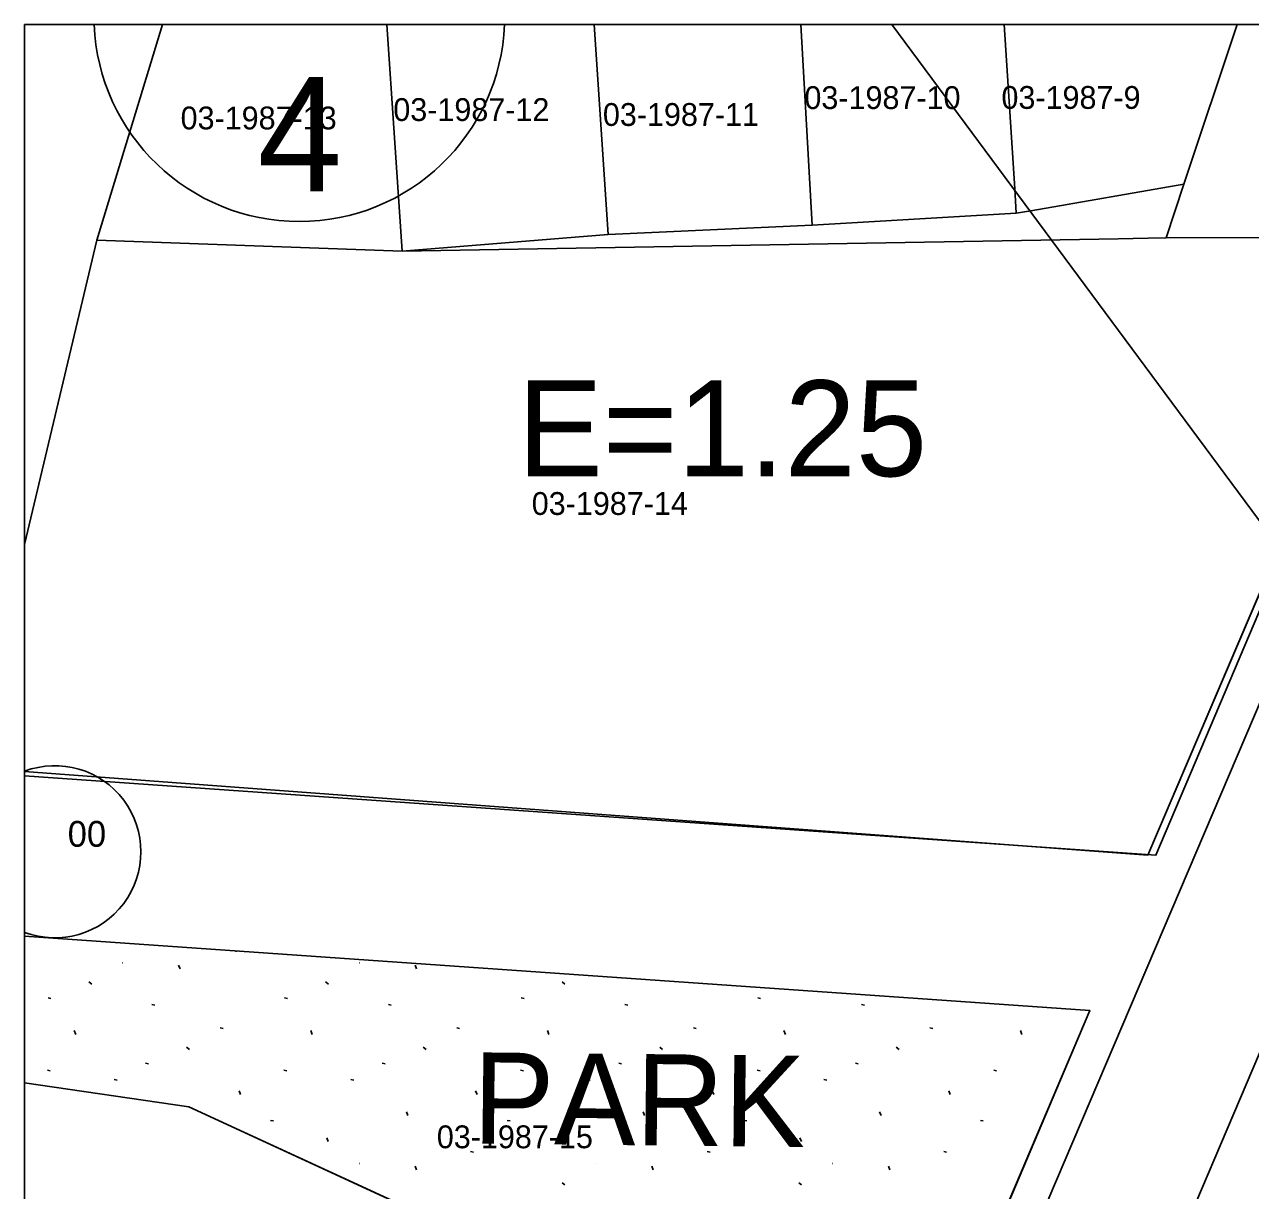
# Model space of a CAD drawing. Extents: x 413946 to 415528, y 4453939 to 4454944.
# Drawn here: x 413945.6 to 413999.3, y 4454892.9 to 4454944 of the extents above; entities that cross this region are included whole.
import ezdxf

# ---------------------------------------------------------------- set-up
doc = ezdxf.new("R2010")
doc.units = 0
for name, color, linetype in [('0_KADASTRO', 7, 'Continuous'), ('0_ÇERÇEVE', 7, 'Continuous'), ('KST_ENERJI_NAKIL_HAT', 7, 'Continuous'), ('Level 28', 7, 'Continuous'), ('Level 33', 7, 'Continuous'), ('Level 41', 7, 'Continuous'), ('Level 54', 7, 'Continuous'), ('Level 62', 7, 'Continuous'), ('SEMBOL', 7, 'Continuous')]:
    doc.layers.add(name, color=color, linetype=linetype)

msp = doc.modelspace()

# ---------------------------------------------------------------- linework, layer by layer
at = {"layer": '0_KADASTRO'}
for points in [[(413945.566, 4454921.163), (413945.566, 4454943.957), (413951.612, 4454943.957)], [(413951.612, 4454943.957), (413948.73, 4454934.5), (413945.566, 4454921.163)], [(413961.44, 4454943.957), (413962.11, 4454934.03), (413948.73, 4454934.5), (413951.612, 4454943.957)], [(413951.612, 4454943.957), (413961.44, 4454943.957)], [(413961.44, 4454943.957), (413970.525, 4454943.957)], [(413970.525, 4454943.957), (413971.15, 4454934.76), (413962.11, 4454934.03), (413961.44, 4454943.957)], [(413970.525, 4454943.957), (413979.593, 4454943.957)], [(413979.593, 4454943.957), (413980.08, 4454935.16), (413971.15, 4454934.76), (413970.525, 4454943.957)], [(413979.593, 4454943.957), (413988.501, 4454943.957)], [(413988.501, 4454943.957), (413988.96, 4454936.76), (413989.02, 4454935.69), (413980.08, 4454935.16), (413979.593, 4454943.957)], [(413988.501, 4454943.957), (413998.704, 4454943.957)], [(413998.704, 4454943.957), (413996.37, 4454936.96), (413989.67, 4454935.79), (413989.02, 4454935.69), (413988.96, 4454936.76), (413988.501, 4454943.957)], [(414010.602, 4454943.957), (414006.63, 4454934.62), (413995.6, 4454934.61), (413996.37, 4454936.96), (413998.704, 4454943.957)], [(413998.704, 4454943.957), (414010.602, 4454943.957)], [(413945.566, 4454921.163), (413948.73, 4454934.5), (413962.11, 4454934.03), (413993.49, 4454934.57), (413994.81, 4454934.6), (413995.6, 4454934.61), (414006.63, 4454934.62), (414001.63, 4454922.83), (413995.15, 4454907.55), (413945.566, 4454911.024)], [(413945.566, 4454911.024), (413945.566, 4454921.163)], [(413945.566, 4454897.575), (413945.566, 4454904)], [(413945.566, 4454904), (413992.26, 4454900.74), (413984.29, 4454882), (413952.76, 4454896.53), (413945.566, 4454897.575)]]:
    msp.add_lwpolyline(points, dxfattribs=at)
at = {"layer": '0_ÇERÇEVE'}
msp.add_lwpolyline([(413945.566, 4454943.957), (415494.137, 4454943.957), (415494.137, 4453939.478), (413945.566, 4453939.478)], close=True, dxfattribs=at)
at = {"layer": 'KST_ENERJI_NAKIL_HAT'}
msp.add_line((414041.874, 4454865.239), (413983.573, 4454943.957), dxfattribs=at)
at = {"layer": 'Level 28'}
for p, q in [((414010.329, 4454943.957), (413994.794, 4454907.558)), ((413994.794, 4454907.558), (413945.566, 4454911.228)), ((413945.566, 4454904), (413992.26, 4454900.74)), ((413992.26, 4454900.74), (413984.29, 4454882)), ((413952.76, 4454896.53), (413945.566, 4454897.575)), ((413984.29, 4454882), (413952.76, 4454896.53))]:
    msp.add_line(p, q, dxfattribs=at)
at = {"layer": 'Level 41'}
for p, q in [((413954.818, 4454903.354), (413954.874, 4454903.343)), ((413954.818, 4454903.354), (413954.874, 4454903.343)), ((413949.864, 4454902.843), (413949.872, 4454902.841)), ((413949.864, 4454902.843), (413949.872, 4454902.841)), ((413960.232, 4454902.843), (413960.24, 4454902.841)), ((413960.232, 4454902.843), (413960.24, 4454902.841)), ((413952.383, 4454902.573), (413952.319, 4454902.735)), ((413952.383, 4454902.573), (413952.319, 4454902.735)), ((413962.751, 4454902.573), (413962.687, 4454902.735)), ((413962.751, 4454902.573), (413962.687, 4454902.735)), ((413948.389, 4454902.004), (413948.516, 4454901.906)), ((413948.389, 4454902.004), (413948.516, 4454901.906)), ((413958.757, 4454902.004), (413958.884, 4454901.906)), ((413958.757, 4454902.004), (413958.884, 4454901.906)), ((413969.125, 4454902.004), (413969.252, 4454901.906)), ((413969.125, 4454902.004), (413969.252, 4454901.906)), ((413946.595, 4454901.299), (413946.721, 4454901.275)), ((413946.595, 4454901.299), (413946.721, 4454901.275)), ((413956.963, 4454901.299), (413957.089, 4454901.275)), ((413956.963, 4454901.299), (413957.089, 4454901.275)), ((413967.331, 4454901.299), (413967.457, 4454901.275)), ((413967.331, 4454901.299), (413967.457, 4454901.275)), ((413977.699, 4454901.299), (413977.825, 4454901.275)), ((413977.699, 4454901.299), (413977.825, 4454901.275)), ((413951.143, 4454901.005), (413951.27, 4454900.982)), ((413951.143, 4454901.005), (413951.27, 4454900.982)), ((413961.511, 4454901.005), (413961.638, 4454900.982)), ((413961.511, 4454901.005), (413961.638, 4454900.982)), ((413971.879, 4454901.005), (413972.006, 4454900.982)), ((413971.879, 4454901.005), (413972.006, 4454900.982)), ((413982.247, 4454901.005), (413982.374, 4454900.982)), ((413982.247, 4454901.005), (413982.374, 4454900.982)), ((413947.808, 4454899.701), (413947.743, 4454899.864)), ((413947.808, 4454899.701), (413947.743, 4454899.864)), ((413954.143, 4454899.981), (413954.268, 4454899.956)), ((413954.143, 4454899.981), (413954.268, 4454899.956)), ((413958.176, 4454899.701), (413958.111, 4454899.864)), ((413958.176, 4454899.701), (413958.111, 4454899.864)), ((413964.511, 4454899.981), (413964.636, 4454899.956)), ((413964.511, 4454899.981), (413964.636, 4454899.956)), ((413968.544, 4454899.701), (413968.479, 4454899.864)), ((413968.544, 4454899.701), (413968.479, 4454899.864)), ((413974.879, 4454899.981), (413975.004, 4454899.956)), ((413974.879, 4454899.981), (413975.004, 4454899.956)), ((413978.912, 4454899.701), (413978.847, 4454899.864)), ((413978.912, 4454899.701), (413978.847, 4454899.864)), ((413985.247, 4454899.981), (413985.372, 4454899.956)), ((413985.247, 4454899.981), (413985.372, 4454899.956)), ((413989.28, 4454899.701), (413989.215, 4454899.864)), ((413989.28, 4454899.701), (413989.215, 4454899.864)), ((413952.668, 4454899.143), (413952.795, 4454899.044)), ((413952.668, 4454899.143), (413952.795, 4454899.044)), ((413963.036, 4454899.143), (413963.163, 4454899.044)), ((413963.036, 4454899.143), (413963.163, 4454899.044)), ((413973.404, 4454899.143), (413973.531, 4454899.044)), ((413973.404, 4454899.143), (413973.531, 4454899.044)), ((413983.772, 4454899.143), (413983.899, 4454899.044)), ((413983.772, 4454899.143), (413983.899, 4454899.044)), ((413946.568, 4454898.133), (413946.695, 4454898.11)), ((413946.568, 4454898.133), (413946.695, 4454898.11)), ((413950.873, 4454898.437), (413950.999, 4454898.414)), ((413950.873, 4454898.437), (413950.999, 4454898.414)), ((413956.936, 4454898.133), (413957.063, 4454898.11)), ((413956.936, 4454898.133), (413957.063, 4454898.11)), ((413961.241, 4454898.437), (413961.367, 4454898.414)), ((413961.241, 4454898.437), (413961.367, 4454898.414)), ((413967.304, 4454898.133), (413967.431, 4454898.11)), ((413967.304, 4454898.133), (413967.431, 4454898.11)), ((413971.609, 4454898.437), (413971.735, 4454898.414)), ((413971.609, 4454898.437), (413971.735, 4454898.414)), ((413977.672, 4454898.133), (413977.799, 4454898.11)), ((413977.672, 4454898.133), (413977.799, 4454898.11)), ((413981.977, 4454898.437), (413982.103, 4454898.414)), ((413981.977, 4454898.437), (413982.103, 4454898.414)), ((413988.04, 4454898.133), (413988.167, 4454898.11)), ((413988.04, 4454898.133), (413988.167, 4454898.11)), ((413949.497, 4454897.724), (413949.624, 4454897.699)), ((413949.497, 4454897.724), (413949.624, 4454897.699)), ((413959.865, 4454897.724), (413959.992, 4454897.699)), ((413959.865, 4454897.724), (413959.992, 4454897.699)), ((413970.233, 4454897.724), (413970.36, 4454897.699)), ((413970.233, 4454897.724), (413970.36, 4454897.699)), ((413980.601, 4454897.724), (413980.728, 4454897.699)), ((413980.601, 4454897.724), (413980.728, 4454897.699)), ((413990.969, 4454897.724), (413990.977, 4454897.722)), ((413990.969, 4454897.724), (413990.977, 4454897.722)), ((413955.033, 4454897.064), (413954.967, 4454897.227)), ((413955.033, 4454897.064), (413954.967, 4454897.227)), ((413965.401, 4454897.064), (413965.335, 4454897.227)), ((413965.401, 4454897.064), (413965.335, 4454897.227)), ((413975.769, 4454897.064), (413975.703, 4454897.227)), ((413975.769, 4454897.064), (413975.703, 4454897.227)), ((413986.137, 4454897.064), (413986.071, 4454897.227)), ((413986.137, 4454897.064), (413986.071, 4454897.227)), ((413956.352, 4454895.929), (413956.478, 4454895.906)), ((413956.352, 4454895.929), (413956.478, 4454895.906)), ((413962.37, 4454896.15), (413962.305, 4454896.313)), ((413962.37, 4454896.15), (413962.305, 4454896.313)), ((413966.72, 4454895.929), (413966.846, 4454895.906)), ((413966.72, 4454895.929), (413966.846, 4454895.906)), ((413972.738, 4454896.15), (413972.673, 4454896.313)), ((413972.738, 4454896.15), (413972.673, 4454896.313)), ((413977.088, 4454895.929), (413977.214, 4454895.906)), ((413977.088, 4454895.929), (413977.214, 4454895.906)), ((413983.106, 4454896.15), (413983.041, 4454896.313)), ((413983.106, 4454896.15), (413983.041, 4454896.313)), ((413987.456, 4454895.929), (413987.582, 4454895.906)), ((413987.456, 4454895.929), (413987.582, 4454895.906)), ((413958.874, 4454895.001), (413958.81, 4454895.162)), ((413958.874, 4454895.001), (413958.81, 4454895.162)), ((413969.242, 4454895.001), (413969.178, 4454895.162)), ((413969.242, 4454895.001), (413969.178, 4454895.162)), ((413979.61, 4454895.001), (413979.546, 4454895.162)), ((413979.61, 4454895.001), (413979.546, 4454895.162)), ((413965.116, 4454894.562), (413965.242, 4454894.537)), ((413965.116, 4454894.562), (413965.242, 4454894.537)), ((413975.484, 4454894.562), (413975.61, 4454894.537)), ((413975.484, 4454894.562), (413975.61, 4454894.537)), ((413985.852, 4454894.562), (413985.978, 4454894.537)), ((413985.852, 4454894.562), (413985.978, 4454894.537)), ((413960.232, 4454894.037), (413960.24, 4454894.035)), ((413960.232, 4454894.037), (413960.24, 4454894.035)), ((413962.751, 4454893.767), (413962.687, 4454893.929)), ((413962.751, 4454893.767), (413962.687, 4454893.929)), ((413970.6, 4454894.037), (413970.608, 4454894.035)), ((413970.6, 4454894.037), (413970.608, 4454894.035)), ((413973.119, 4454893.767), (413973.055, 4454893.929)), ((413973.119, 4454893.767), (413973.055, 4454893.929)), ((413980.968, 4454894.037), (413980.976, 4454894.035)), ((413980.968, 4454894.037), (413980.976, 4454894.035)), ((413983.487, 4454893.767), (413983.423, 4454893.929)), ((413983.487, 4454893.767), (413983.423, 4454893.929)), ((413969.125, 4454893.198), (413969.252, 4454893.1)), ((413969.125, 4454893.198), (413969.252, 4454893.1)), ((413979.493, 4454893.198), (413979.62, 4454893.1)), ((413979.493, 4454893.198), (413979.62, 4454893.1))]:
    msp.add_line(p, q, dxfattribs=at)
at = {"layer": 'Level 54'}
for points in [[(414010.329, 4454943.957), (413994.794, 4454907.558), (413945.566, 4454911.228)], [(413945.566, 4454911.228), (413945.566, 4454943.957), (414010.329, 4454943.957)]]:
    msp.add_lwpolyline(points, dxfattribs=at)
at = {"layer": 'Level 62'}
for p, q in [((413980.793, 4454869.825), (414012.354, 4454943.957)), ((413986.313, 4454867.474), (414018.875, 4454943.957))]:
    msp.add_line(p, q, dxfattribs=at)
at = {"layer": 'SEMBOL'}
for points in [[(413966.601, 4454943.957), (413948.616, 4454943.957)], [(413945.566, 4454911.233), (413945.566, 4454904.173)]]:
    msp.add_lwpolyline(points, dxfattribs=at)
for centre, radius, start, end in [((413957.609, 4454944.323), 9, 182.3341, 357.6659), ((413946.894, 4454907.703), 3.772, 249.3856, 110.6144)]:
    msp.add_arc(centre, radius, start, end, dxfattribs=at)

# ---------------------------------------------------------------- texts
at = {"layer": '0_KADASTRO'}
for s, p in [('03-1987-10', (413979.745, 4454940.253)), ('03-1987-9', (413988.38, 4454940.26)), ('03-1987-12', (413961.728, 4454939.729)), ('03-1987-11', (413970.913, 4454939.513)), ('03-1987-13', (413952.406, 4454939.361)), ('03-1987-14', (413967.795, 4454922.465)), ('03-1987-15', (413963.635, 4454894.711))]:
    msp.add_text(s, height=1, dxfattribs=at).set_placement(p)
at = {"layer": 'Level 33'}
msp.add_text('PARK', height=4, rotation=359.4136, dxfattribs=at).set_placement((413965.197, 4454894.915))
at = {"layer": 'SEMBOL'}
for s, height, p in [('4', 5, (413955.771, 4454936.65)), ('E=1.25', 4.2, (413967.167, 4454924.162)), ('00', 1.1315, (413947.459, 4454907.922))]:
    msp.add_text(s, height=height, dxfattribs=at).set_placement(p)

doc.saveas('drawing.dxf')
